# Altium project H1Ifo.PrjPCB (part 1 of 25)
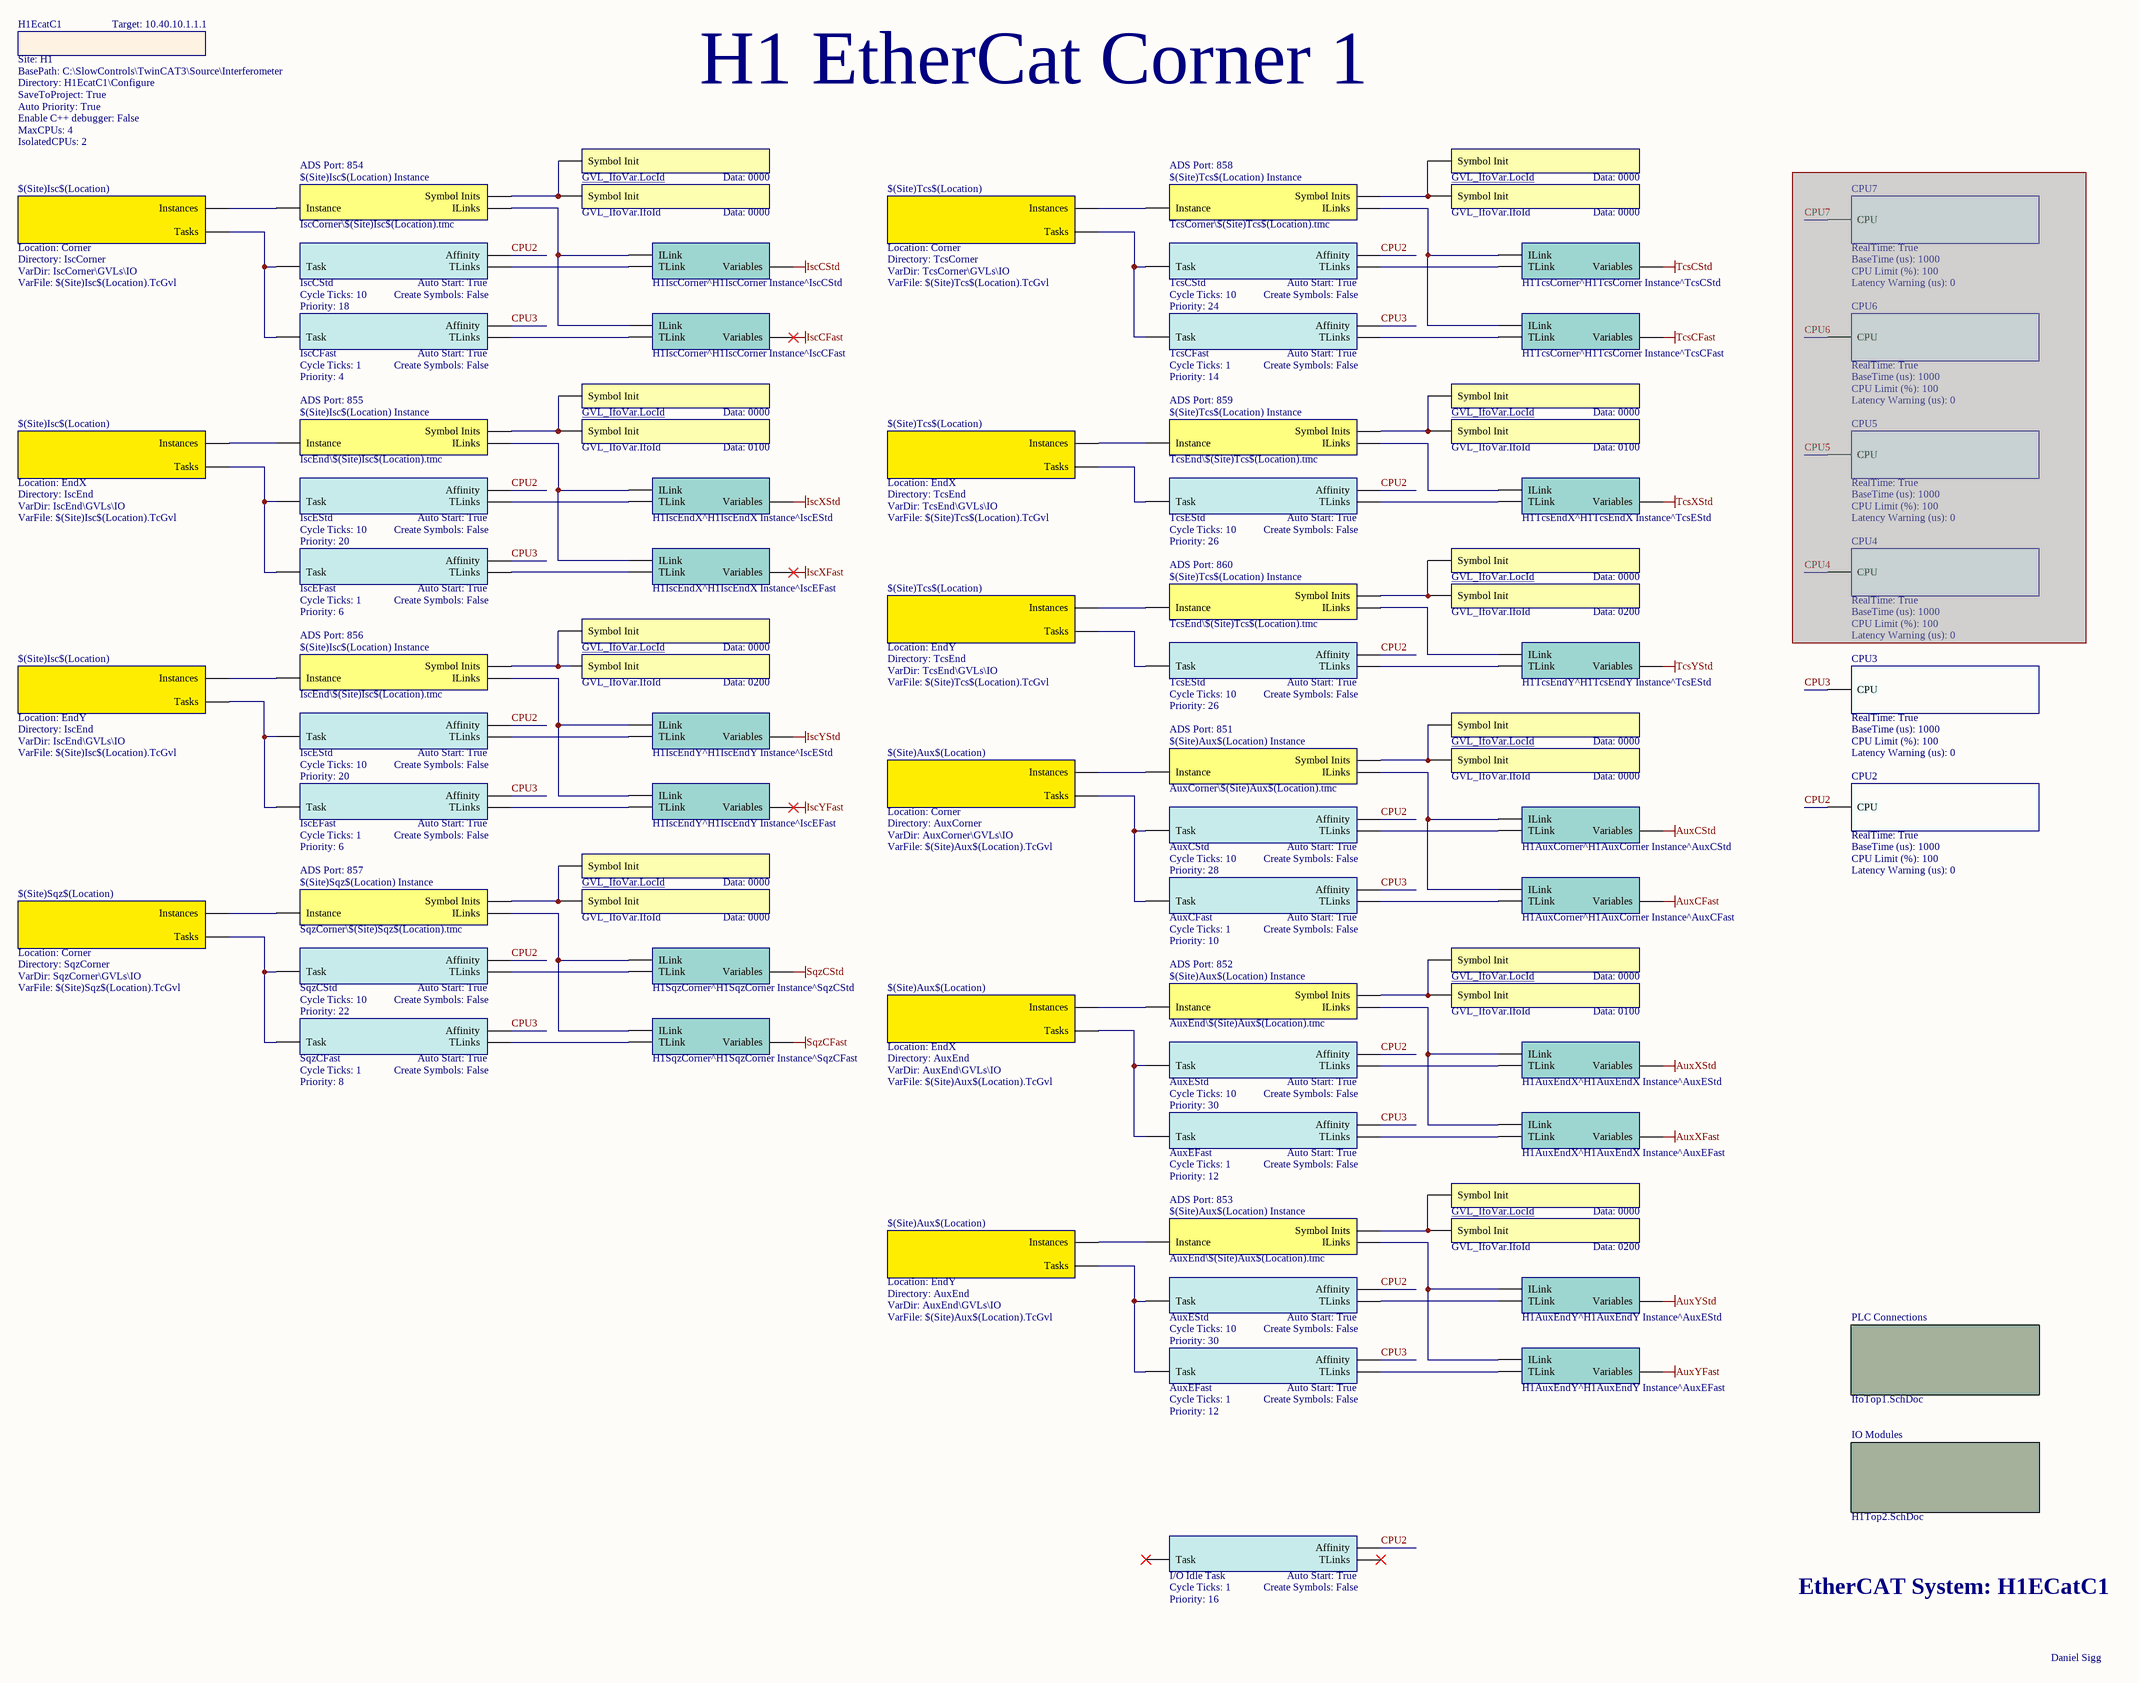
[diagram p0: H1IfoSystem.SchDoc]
Title: D1800185; Revision: 4
33 sheets, 2126 parts. Net scope: flat (ports and power ports of the same name join across sheets).
Sheets:
  H1IfoSystem.SchDoc
    IO Modules = H1Top2.SchDoc
      MSR Corner = IfoMsr1.SchDoc
      Aux Corner = IfoAux1.SchDoc
      PSL IO TCS Corner = IfoPsl.SchDoc
      TCS Corner = IfoTcs1.SchDoc
      ISC Common = IfoIsc1.SchDoc
      ISC Corner 2 = IfoIsc2A.SchDoc
      ISC Corner 2 = IfoIsc2B.SchDoc
      ISC Corner 3 = IfoIsc3.SchDoc
      ISC Corner 4 = IfoIsc4.SchDoc
      ISC Corner 5 = IfoIsc5A.SchDoc
      ISC Corner 5 = IfoIsc5B.SchDoc
      ISC Corner 6 = IfoIsc6.SchDoc
      SQZ Common = IfoSqz1.SchDoc
      SQZ 2 = IfoSqz2.SchDoc
      SQZ 3 = IfoSqz3A.SchDoc
      SQZ 3 = IfoSqz3B.SchDoc
      Remote EX = IfoEndX0.SchDoc
      EX Common = IfoEndX1.SchDoc
      EX 2 = IfoEndX2.SchDoc
      EX 3 = IfoEndX3.SchDoc
      Remote EY = IfoEndY0.SchDoc
      EY Common = IfoEndY1.SchDoc
      EY 2 = IfoEndY2.SchDoc
      EY 3 = IfoEndY3.SchDoc
      EX Aux = IfoEndXAux.SchDoc
      EY Aux = IfoEndYAux.SchDoc
      SQZ 4 = IfoSqz4A.SchDoc
      SQZ 4 = IfoSqz4B.SchDoc
      FC End = IfoFcEnd.SchDoc
      SQZ 5 = IfoSqz5.SchDoc
    PLC Connections = IfoTop1.SchDoc

## Sheet H1IfoSystem.SchDoc: D1800185
size C; Engineer: Daniel Sigg; DocumentNumber: 1; Revision: 4; SheetNumber: 1; SheetTotal: 31

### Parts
CPU2  RealTime: True  BaseTime (us): 1000  CPU Limit (%): 100  Latency Warning (us): 0  (hidden comment: CPU)  (mechanical)
CPU3  RealTime: True  BaseTime (us): 1000  CPU Limit (%): 100  Latency Warning (us): 0  (hidden comment: CPU)  (mechanical)
CPU4  RealTime: True  BaseTime (us): 1000  CPU Limit (%): 100  Latency Warning (us): 0  (hidden comment: CPU)  (mechanical)  (masked out: inside a compile mask, not in the netlist)
CPU5  RealTime: True  BaseTime (us): 1000  CPU Limit (%): 100  Latency Warning (us): 0  (hidden comment: CPU)  (mechanical)  (masked out: inside a compile mask, not in the netlist)
CPU6  RealTime: True  BaseTime (us): 1000  CPU Limit (%): 100  Latency Warning (us): 0  (hidden comment: CPU)  (mechanical)  (masked out: inside a compile mask, not in the netlist)
CPU7  RealTime: True  BaseTime (us): 1000  CPU Limit (%): 100  Latency Warning (us): 0  (hidden comment: CPU)  (mechanical)  (masked out: inside a compile mask, not in the netlist)
I1  $(Site)Isc$(Location) Instance  ADS Port: 854  Filename: IscCorner\$(Site)Isc$(Location).tmc  (mechanical)
I2  $(Site)Isc$(Location) Instance  ADS Port: 855  Filename: IscEnd\$(Site)Isc$(Location).tmc  (mechanical)
I3  $(Site)Isc$(Location) Instance  ADS Port: 856  Filename: IscEnd\$(Site)Isc$(Location).tmc  (mechanical)
I4  $(Site)Sqz$(Location) Instance  ADS Port: 857  Filename: SqzCorner\$(Site)Sqz$(Location).tmc  (mechanical)
I5  $(Site)Tcs$(Location) Instance  ADS Port: 858  Filename: TcsCorner\$(Site)Tcs$(Location).tmc  (mechanical)
I6  $(Site)Tcs$(Location) Instance  ADS Port: 859  Filename: TcsEnd\$(Site)Tcs$(Location).tmc  (mechanical)
I7  $(Site)Tcs$(Location) Instance  ADS Port: 860  Filename: TcsEnd\$(Site)Tcs$(Location).tmc  (mechanical)
I8  $(Site)Aux$(Location) Instance  ADS Port: 851  Filename: AuxCorner\$(Site)Aux$(Location).tmc  (mechanical)
I9  $(Site)Aux$(Location) Instance  ADS Port: 852  Filename: AuxEnd\$(Site)Aux$(Location).tmc  (mechanical)
I10  $(Site)Aux$(Location) Instance  ADS Port: 853  Filename: AuxEnd\$(Site)Aux$(Location).tmc  (mechanical)
PLC1  $(Site)Isc$(Location)  Directory: IscCorner  Location: Corner  VarFile: $(Site)Isc$(Location).TcGvl  VarDir: IscCorner\GVLs\IO  (mechanical)
PLC2  $(Site)Isc$(Location)  Directory: IscEnd  Location: EndX  VarFile: $(Site)Isc$(Location).TcGvl  VarDir: IscEnd\GVLs\IO  (mechanical)
PLC3  $(Site)Isc$(Location)  Directory: IscEnd  Location: EndY  VarFile: $(Site)Isc$(Location).TcGvl  VarDir: IscEnd\GVLs\IO  (mechanical)
PLC4  $(Site)Sqz$(Location)  Directory: SqzCorner  Location: Corner  VarFile: $(Site)Sqz$(Location).TcGvl  VarDir: SqzCorner\GVLs\IO  (mechanical)
PLC5  $(Site)Tcs$(Location)  Directory: TcsCorner  Location: Corner  VarFile: $(Site)Tcs$(Location).TcGvl  VarDir: TcsCorner\GVLs\IO  (mechanical)
PLC6  $(Site)Tcs$(Location)  Directory: TcsEnd  Location: EndX  VarFile: $(Site)Tcs$(Location).TcGvl  VarDir: TcsEnd\GVLs\IO  (mechanical)
PLC7  $(Site)Tcs$(Location)  Directory: TcsEnd  Location: EndY  VarFile: $(Site)Tcs$(Location).TcGvl  VarDir: TcsEnd\GVLs\IO  (mechanical)
PLC8  $(Site)Aux$(Location)  Directory: AuxCorner  Location: Corner  VarFile: $(Site)Aux$(Location).TcGvl  VarDir: AuxCorner\GVLs\IO  (mechanical)
PLC9  $(Site)Aux$(Location)  Directory: AuxEnd  Location: EndX  VarFile: $(Site)Aux$(Location).TcGvl  VarDir: AuxEnd\GVLs\IO  (mechanical)
PLC10  $(Site)Aux$(Location)  Directory: AuxEnd  Location: EndY  VarFile: $(Site)Aux$(Location).TcGvl  VarDir: AuxEnd\GVLs\IO  (mechanical)
S1  GVL_IfoVar.LocId  Data: 0000  (mechanical)
S2  GVL_IfoVar.IfoId  Data: 0000  (mechanical)
S3  GVL_IfoVar.LocId  Data: 0000  (mechanical)
S4  GVL_IfoVar.IfoId  Data: 0100  (mechanical)
S5  GVL_IfoVar.LocId  Data: 0000  (mechanical)
S6  GVL_IfoVar.IfoId  Data: 0200  (mechanical)
S7  GVL_IfoVar.LocId  Data: 0000  (mechanical)
S8  GVL_IfoVar.IfoId  Data: 0000  (mechanical)
S9  GVL_IfoVar.LocId  Data: 0000  (mechanical)
S10  GVL_IfoVar.IfoId  Data: 0000  (mechanical)
S11  GVL_IfoVar.LocId  Data: 0000  (mechanical)
S12  GVL_IfoVar.IfoId  Data: 0100  (mechanical)
S13  GVL_IfoVar.LocId  Data: 0000  (mechanical)
S14  GVL_IfoVar.IfoId  Data: 0200  (mechanical)
S15  GVL_IfoVar.LocId  Data: 0000  (mechanical)
S16  GVL_IfoVar.IfoId  Data: 0000  (mechanical)
S17  GVL_IfoVar.LocId  Data: 0000  (mechanical)
S18  GVL_IfoVar.IfoId  Data: 0100  (mechanical)
S19  GVL_IfoVar.LocId  Data: 0000  (mechanical)
S20  GVL_IfoVar.IfoId  Data: 0200  (mechanical)
System  H1EcatC1  Auto Priority: True  Enable C++ debugger: False  Directory: H1EcatC1\Configure  Target: 10.40.10.1.1.1  MaxCPUs: 4  IsolatedCPUs: 2  BasePath: C:\SlowControls\TwinCAT3\Source\Interferometer  Site: H1  (mechanical)
T1  IscCStd  Priority: 18  Cycle Ticks: 10  Auto Start: True  Create Symbols: False  (mechanical)
T2  IscCFast  Priority: 4  Cycle Ticks: 1  Auto Start: True  Create Symbols: False  (mechanical)
T3  IscEStd  Priority: 20  Cycle Ticks: 10  Auto Start: True  Create Symbols: False  (mechanical)
T4  IscEFast  Priority: 6  Cycle Ticks: 1  Auto Start: True  Create Symbols: False  (mechanical)
T5  IscEStd  Priority: 20  Cycle Ticks: 10  Auto Start: True  Create Symbols: False  (mechanical)
T6  IscEFast  Priority: 6  Cycle Ticks: 1  Auto Start: True  Create Symbols: False  (mechanical)
T7  SqzCStd  Priority: 22  Cycle Ticks: 10  Auto Start: True  Create Symbols: False  (mechanical)
T8  SqzCFast  Priority: 8  Cycle Ticks: 1  Auto Start: True  Create Symbols: False  (mechanical)
T9  H1IscCorner^H1IscCorner Instance^IscCStd  (mechanical)
T10  H1IscCorner^H1IscCorner Instance^IscCFast  (mechanical)
T11  H1IscEndX^H1IscEndX Instance^IscEStd  (mechanical)
T12  H1IscEndX^H1IscEndX Instance^IscEFast  (mechanical)
T13  H1IscEndY^H1IscEndY Instance^IscEStd  (mechanical)
T14  H1IscEndY^H1IscEndY Instance^IscEFast  (mechanical)
T15  H1SqzCorner^H1SqzCorner Instance^SqzCStd  (mechanical)
T16  H1SqzCorner^H1SqzCorner Instance^SqzCFast  (mechanical)
T17  TcsCStd  Priority: 24  Cycle Ticks: 10  Auto Start: True  Create Symbols: False  (mechanical)
T18  TcsEStd  Priority: 26  Cycle Ticks: 10  Auto Start: True  Create Symbols: False  (mechanical)
T19  TcsEStd  Priority: 26  Cycle Ticks: 10  Auto Start: True  Create Symbols: False  (mechanical)
T20  AuxCStd  Priority: 28  Cycle Ticks: 10  Auto Start: True  Create Symbols: False  (mechanical)
T21  AuxCFast  Priority: 10  Cycle Ticks: 1  Auto Start: True  Create Symbols: False  (mechanical)
T22  AuxEStd  Priority: 30  Cycle Ticks: 10  Auto Start: True  Create Symbols: False  (mechanical)
T23  AuxEFast  Priority: 12  Cycle Ticks: 1  Auto Start: True  Create Symbols: False  (mechanical)
T24  AuxEStd  Priority: 30  Cycle Ticks: 10  Auto Start: True  Create Symbols: False  (mechanical)
T25  AuxEFast  Priority: 12  Cycle Ticks: 1  Auto Start: True  Create Symbols: False  (mechanical)
T26  I/O Idle Task  Priority: 16  Cycle Ticks: 1  Auto Start: True  Create Symbols: False  (mechanical)
T27  H1TcsCorner^H1TcsCorner Instance^TcsCStd  (mechanical)
T28  H1TcsEndX^H1TcsEndX Instance^TcsEStd  (mechanical)
T29  H1TcsEndY^H1TcsEndY Instance^TcsEStd  (mechanical)
T30  H1AuxCorner^H1AuxCorner Instance^AuxCStd  (mechanical)
T31  H1AuxCorner^H1AuxCorner Instance^AuxCFast  (mechanical)
T32  H1AuxEndX^H1AuxEndX Instance^AuxEStd  (mechanical)
T33  H1AuxEndX^H1AuxEndX Instance^AuxEFast  (mechanical)
T34  H1AuxEndY^H1AuxEndY Instance^AuxEStd  (mechanical)
T35  H1AuxEndY^H1AuxEndY Instance^AuxEFast  (mechanical)
T36  TcsCFast  Priority: 14  Cycle Ticks: 1  Auto Start: True  Create Symbols: False  (mechanical)
T37  H1TcsCorner^H1TcsCorner Instance^TcsCFast  (mechanical)

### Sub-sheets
IO Modules = H1Top2.SchDoc: no entries
PLC Connections = IfoTop1.SchDoc: no entries

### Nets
AuxCFast: T31.0(Variables)
AuxCStd: T30.0(Variables)
AuxXFast: T33.0(Variables)
AuxXStd: T32.0(Variables)
AuxYFast: T35.0(Variables)
AuxYStd: T34.0(Variables)
IscCFast: T10.0(Variables)
IscCStd: T9.0(Variables)
IscXFast: T12.0(Variables)
IscXStd: T11.0(Variables)
IscYFast: T14.0(Variables)
IscYStd: T13.0(Variables)
SqzCFast: T16.0(Variables)
SqzCStd: T15.0(Variables)
TcsCFast: T37.0(Variables)
TcsCStd: T27.0(Variables)
TcsXStd: T28.0(Variables)
TcsYStd: T29.0(Variables)
CPU2: CPU2.0(CPU) T1.1(Affinity) T3.1(Affinity) T5.1(Affinity) T7.1(Affinity) T17.1(Affinity) T18.1(Affinity) T19.1(Affinity) T20.1(Affinity) T22.1(Affinity) T24.1(Affinity) T26.1(Affinity)
CPU3: CPU3.0(CPU) T2.1(Affinity) T4.1(Affinity) T6.1(Affinity) T8.1(Affinity) T21.1(Affinity) T23.1(Affinity) T25.1(Affinity) T36.1(Affinity)
NetI1_0: I1.0(Instance) PLC1.0(Instances)
NetI1_2: I1.2(ILinks) T9.1(ILink) T10.1(ILink)
NetI1_2: I1.2(Symbol_Inits) S1.99(Symbol_Init) S2.99(Symbol_Init)  [a separate net that carries the same name]
NetI2_0: I2.0(Instance) PLC2.0(Instances)
NetI2_2: I2.2(ILinks) T11.1(ILink) T12.1(ILink)
NetI2_2: I2.2(Symbol_Inits) S3.99(Symbol_Init) S4.99(Symbol_Init)  [a separate net that carries the same name]
NetI3_0: I3.0(Instance) PLC3.0(Instances)
NetI3_2: I3.2(ILinks) T13.1(ILink) T14.1(ILink)
NetI3_2: I3.2(Symbol_Inits) S5.99(Symbol_Init) S6.99(Symbol_Init)  [a separate net that carries the same name]
NetI4_0: I4.0(Instance) PLC4.0(Instances)
NetI4_2: I4.2(ILinks) T15.1(ILink) T16.1(ILink)
NetI4_2: I4.2(Symbol_Inits) S7.99(Symbol_Init) S8.99(Symbol_Init)  [a separate net that carries the same name]
NetI5_0: I5.0(Instance) PLC5.0(Instances)
NetI5_2: I5.2(Symbol_Inits) S9.99(Symbol_Init) S10.99(Symbol_Init)
NetI5_2: I5.2(ILinks) T27.1(ILink) T37.1(ILink)  [a separate net that carries the same name]
NetI6_0: I6.0(Instance) PLC6.0(Instances)
NetI6_2: I6.2(ILinks) T28.1(ILink)
NetI6_2: I6.2(Symbol_Inits) S11.99(Symbol_Init) S12.99(Symbol_Init)  [a separate net that carries the same name]
NetI7_0: I7.0(Instance) PLC7.0(Instances)
NetI7_2: I7.2(ILinks) T29.1(ILink)
NetI7_2: I7.2(Symbol_Inits) S13.99(Symbol_Init) S14.99(Symbol_Init)  [a separate net that carries the same name]
NetI8_0: I8.0(Instance) PLC8.0(Instances)
NetI8_2: I8.2(ILinks) T30.1(ILink) T31.1(ILink)
NetI8_2: I8.2(Symbol_Inits) S15.99(Symbol_Init) S16.99(Symbol_Init)  [a separate net that carries the same name]
NetI9_0: I9.0(Instance) PLC9.0(Instances)
NetI9_2: I9.2(ILinks) T32.1(ILink) T33.1(ILink)
NetI9_2: I9.2(Symbol_Inits) S17.99(Symbol_Init) S18.99(Symbol_Init)  [a separate net that carries the same name]
NetI10_0: I10.0(Instance) PLC10.0(Instances)
NetI10_2: I10.2(ILinks) T34.1(ILink) T35.1(ILink)
NetI10_2: I10.2(Symbol_Inits) S19.99(Symbol_Init) S20.99(Symbol_Init)  [a separate net that carries the same name]
NetPLC1_1: PLC1.1(Tasks) T1.0(Task) T2.0(Task)
NetPLC2_1: PLC2.1(Tasks) T3.0(Task) T4.0(Task)
NetPLC3_1: PLC3.1(Tasks) T5.0(Task) T6.0(Task)
NetPLC4_1: PLC4.1(Tasks) T7.0(Task) T8.0(Task)
NetPLC5_1: PLC5.1(Tasks) T17.0(Task) T36.0(Task)
NetPLC6_1: PLC6.1(Tasks) T18.0(Task)
NetPLC7_1: PLC7.1(Tasks) T19.0(Task)
NetPLC8_1: PLC8.1(Tasks) T20.0(Task) T21.0(Task)
NetPLC9_1: PLC9.1(Tasks) T22.0(Task) T23.0(Task)
NetPLC10_1: PLC10.1(Tasks) T24.0(Task) T25.0(Task)
NetT1_2: T1.2(TLinks) T9.2(TLink)
NetT2_2: T2.2(TLinks) T10.2(TLink)
NetT3_2: T3.2(TLinks) T11.2(TLink)
NetT4_2: T4.2(TLinks) T12.2(TLink)
NetT5_2: T5.2(TLinks) T13.2(TLink)
NetT6_2: T6.2(TLinks) T14.2(TLink)
NetT7_2: T7.2(TLinks) T15.2(TLink)
NetT8_2: T8.2(TLinks) T16.2(TLink)
NetT17_2: T17.2(TLinks) T27.2(TLink)
NetT18_2: T18.2(TLinks) T28.2(TLink)
NetT19_2: T19.2(TLinks) T29.2(TLink)
NetT20_2: T20.2(TLinks) T30.2(TLink)
NetT21_2: T21.2(TLinks) T31.2(TLink)
NetT22_2: T22.2(TLinks) T32.2(TLink)
NetT23_2: T23.2(TLinks) T33.2(TLink)
NetT24_2: T24.2(TLinks) T34.2(TLink)
NetT25_2: T25.2(TLinks) T35.2(TLink)
NetT36_2: T36.2(TLinks) T37.2(TLink)

Not connected (* = marked no-connect by the designer): T26 0(Task)* 2(TLinks)*

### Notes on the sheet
- H1 EtherCat Corner 1
- EtherCAT System: H1ECatC1
- Daniel Sigg

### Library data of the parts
CPU2-CPU7 = TwinCATCPU: TwinCAT CPU
I1 = TwinCATInstance: TwinCAT PLC Instance; Symbol Init: QOGVYBPF; PLC: H1IscCorner; Location: Corner
I2 = TwinCATInstance: TwinCAT PLC Instance; Symbol Init: ANWTYMNB; PLC: H1IscEndX; Location: EndX
I3 = TwinCATInstance: TwinCAT PLC Instance; Symbol Init: TKQDQPCD; PLC: H1IscEndY; Location: EndY
I4 = TwinCATInstance: TwinCAT PLC Instance; Symbol Init: JDCVMCFT; PLC: H1SqzCorner; Location: Corner
I5 = TwinCATInstance: TwinCAT PLC Instance; Symbol Init: PQEEGHBX; PLC: H1TcsCorner; Location: Corner
I6 = TwinCATInstance: TwinCAT PLC Instance; Symbol Init: PMAHGRIT; PLC: H1TcsEndX; Location: EndX
I7 = TwinCATInstance: TwinCAT PLC Instance; Symbol Init: QCDHSLLL; PLC: H1TcsEndY; Location: EndY
I8 = TwinCATInstance: TwinCAT PLC Instance; Symbol Init: FOFYGOIF; PLC: H1AuxCorner; Location: Corner
I9 = TwinCATInstance: TwinCAT PLC Instance; Symbol Init: VPBKJCNL; PLC: H1AuxEndX; Location: EndX
I10 = TwinCATInstance: TwinCAT PLC Instance; Symbol Init: HWRHWHNB; PLC: H1AuxEndY; Location: EndY
PLC1 = TwinCATPLC: TwinCAT PLC; Instance: GYFKFSOI
PLC2 = TwinCATPLC: TwinCAT PLC; Instance: EWVUFOBF
PLC3 = TwinCATPLC: TwinCAT PLC; Instance: NJXXMYFB
PLC4 = TwinCATPLC: TwinCAT PLC; Instance: GIVXPOYF
PLC5 = TwinCATPLC: TwinCAT PLC; Instance: MUFDHMNW
PLC6 = TwinCATPLC: TwinCAT PLC; Instance: TPTTRFUS
PLC7 = TwinCATPLC: TwinCAT PLC; Instance: BORUSAKV
PLC8 = TwinCATPLC: TwinCAT PLC; Instance: FFXNWLLD
PLC9 = TwinCATPLC: TwinCAT PLC; Instance: NTIEJDWE
PLC10 = TwinCATPLC: TwinCAT PLC; Instance: KMWKGJTW
S1 = TwinCATSymbol: TwinCAT Symbol Initialization; Next: KBGCXKHJ
S2 S4 S6 S8 S10 S12 S14 S16 S18 S20 = TwinCATSymbol: TwinCAT Symbol Initialization
S3 = TwinCATSymbol: TwinCAT Symbol Initialization; Next: RFHBSAYS
S5 = TwinCATSymbol: TwinCAT Symbol Initialization; Next: YLQCSWVN
S7 = TwinCATSymbol: TwinCAT Symbol Initialization; Next: LKBTSDNS
S9 = TwinCATSymbol: TwinCAT Symbol Initialization; Next: FADMXHAG
S11 = TwinCATSymbol: TwinCAT Symbol Initialization; Next: OKYYBMVQ
S13 = TwinCATSymbol: TwinCAT Symbol Initialization; Next: JGJNILQS
S15 = TwinCATSymbol: TwinCAT Symbol Initialization; Next: FCGACHJI
S17 = TwinCATSymbol: TwinCAT Symbol Initialization; Next: SEHPMEBM
S19 = TwinCATSymbol: TwinCAT Symbol Initialization; Next: LHVAWOAX
System = TwinCATSystem: TwinCAT System
T1 T3 T5 T7 T17-T20 T22 T24 T26 = TwinCATTask: TwinCAT Task; CPU: 2; BaseTime (100ns): 10000
T2 T4 T6 T8 T21 T23 T25 T36 = TwinCATTask: TwinCAT Task; CPU: 3; BaseTime (100ns): 10000
T9-T16 T27-T35 T37 = TwinCATLink: TwinCAT Variable Link

## Sheet H1Top2.SchDoc: D1800185
size C; DocumentNumber: 3; Revision: 4; SheetNumber: 3; SheetTotal: 31; pInstance: Corner
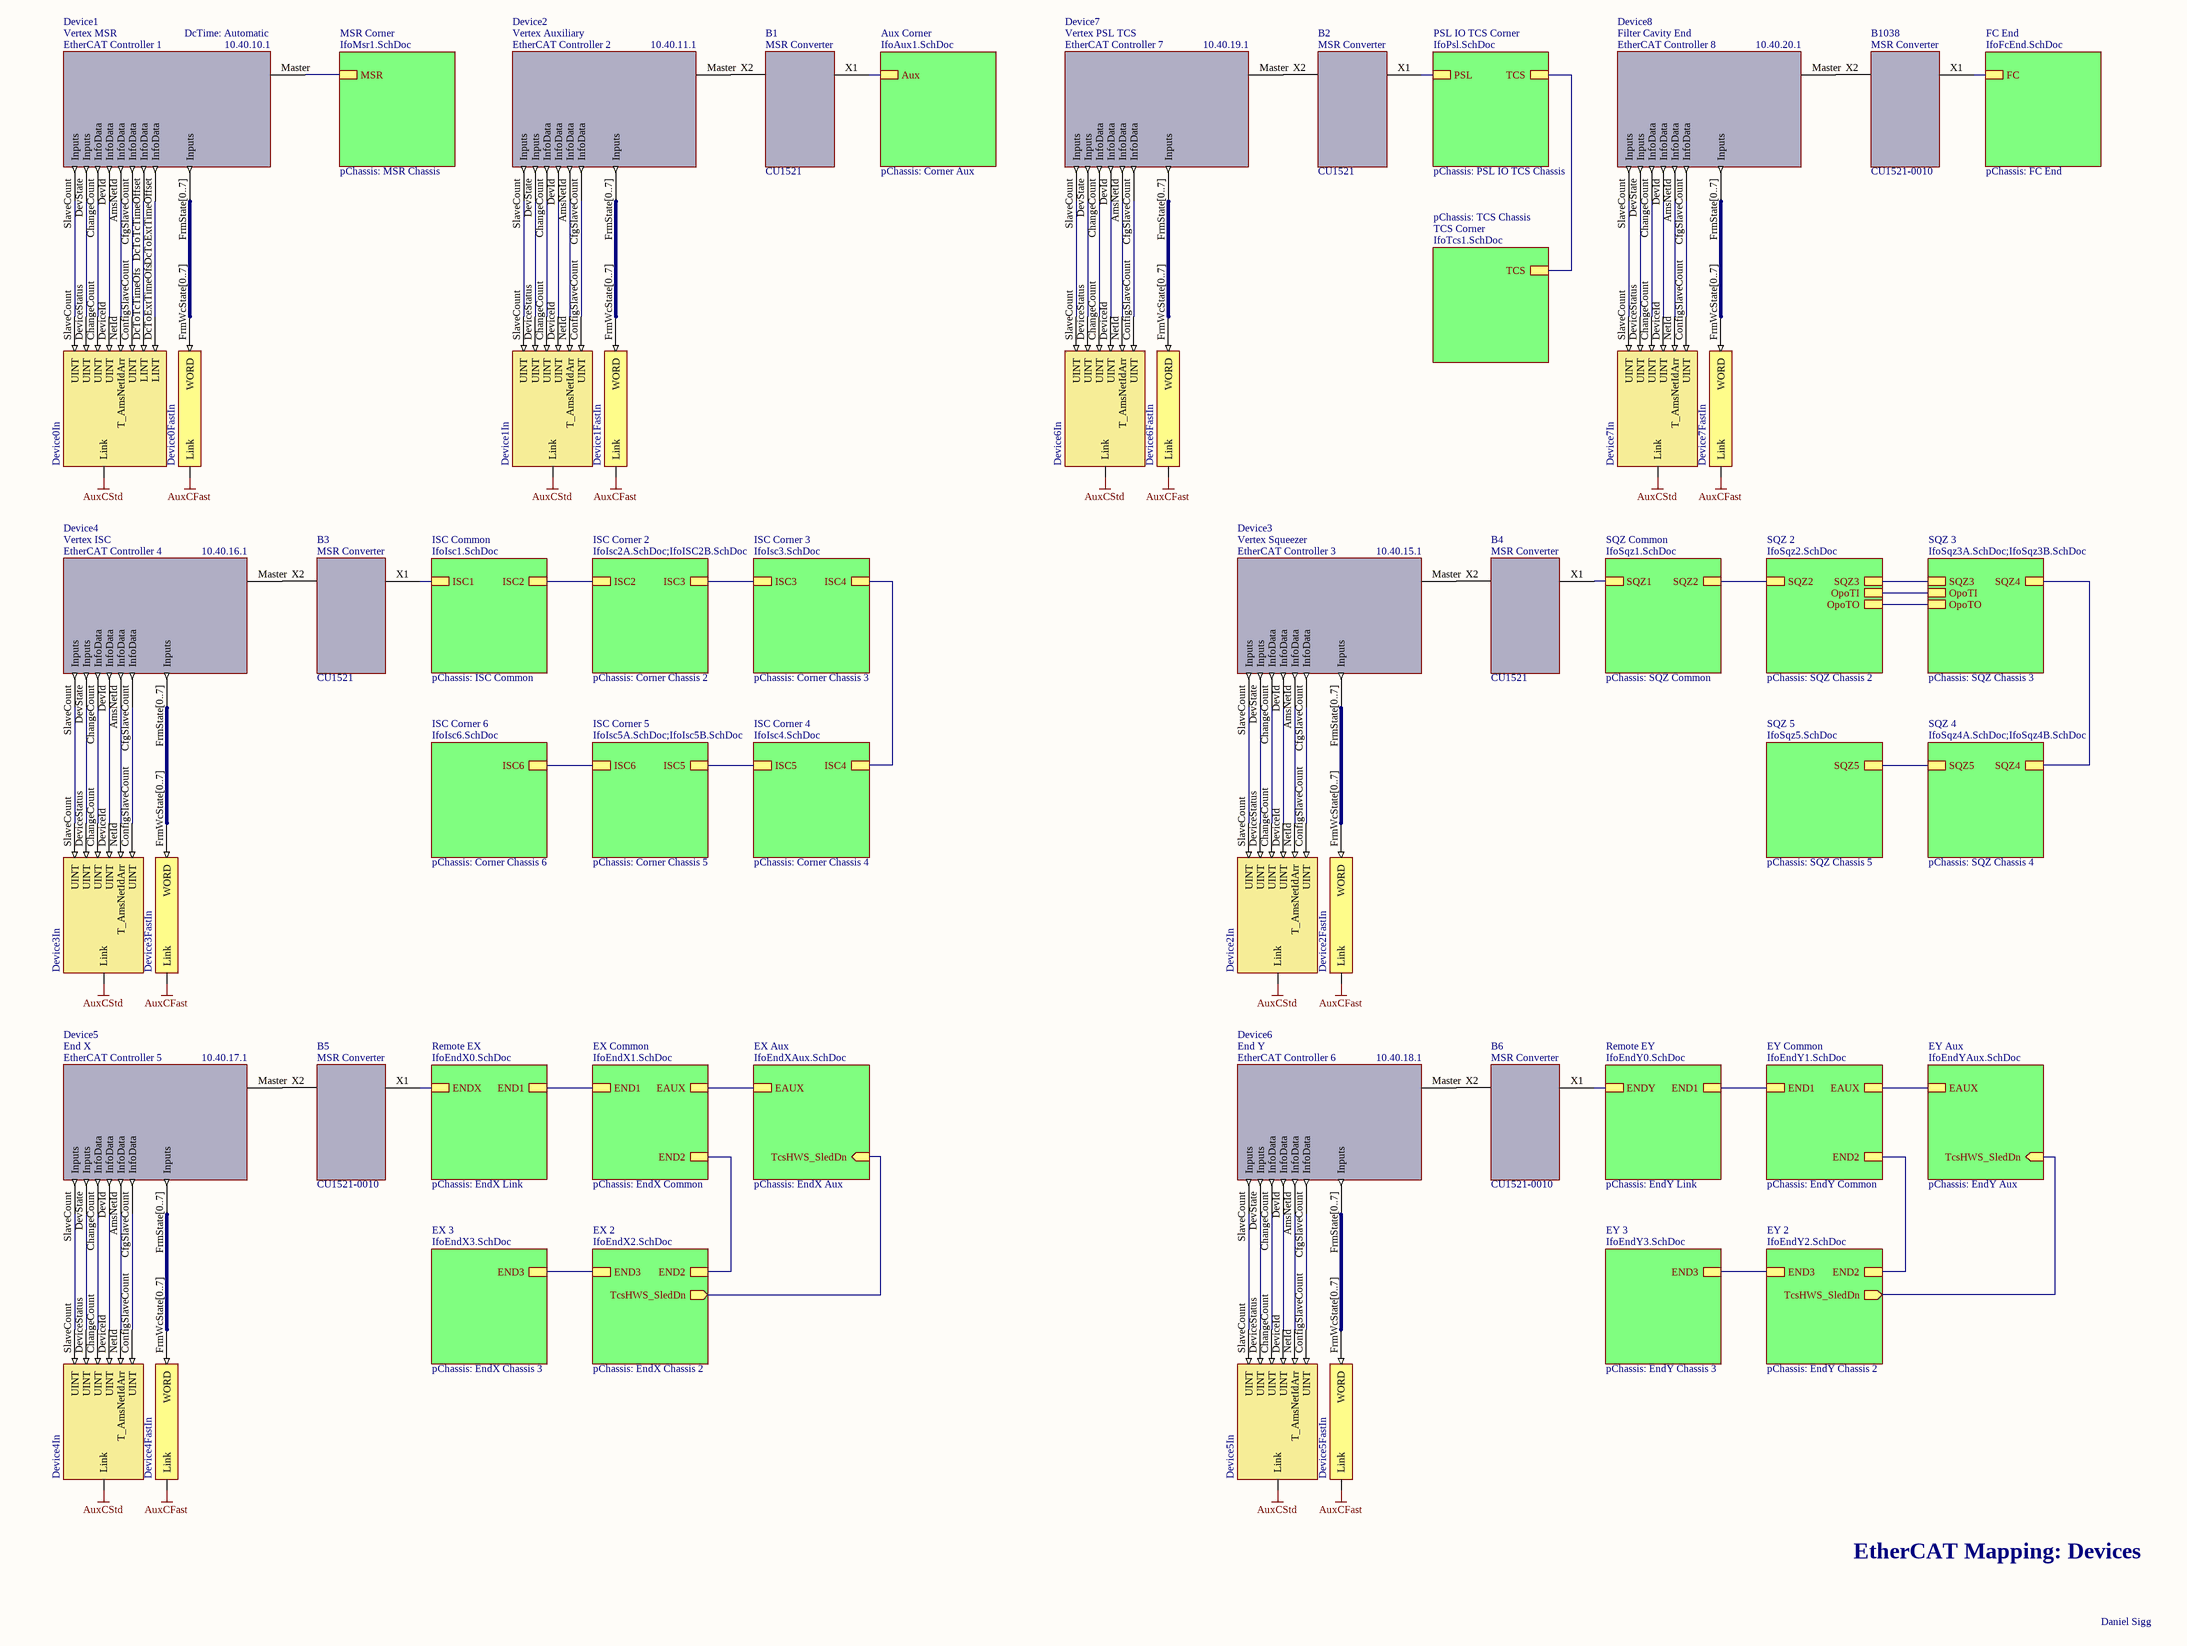
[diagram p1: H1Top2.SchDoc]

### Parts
B1  MSR Converter  Part Number: CU1521  (mechanical)
B2  MSR Converter  Part Number: CU1521  (mechanical)
B3  MSR Converter  Part Number: CU1521  (mechanical)
B4  MSR Converter  Part Number: CU1521  (mechanical)
B5  MSR Converter  Part Number: CU1521-0010  (mechanical)
B6  MSR Converter  Part Number: CU1521-0010  (mechanical)
B1038  MSR Converter  Part Number: CU1521-0010  (mechanical)
Device1  Vertex MSR  DcTime: Automatic  IPAddr: 10.40.10.1  DeviceDesc: EtherCAT Controller 1  (mechanical)
Device2  Vertex Auxiliary  IPAddr: 10.40.11.1  DeviceDesc: EtherCAT Controller 2  (mechanical)
Device3  Vertex Squeezer  IPAddr: 10.40.15.1  DeviceDesc: EtherCAT Controller 3  (mechanical)
Device4  Vertex ISC  IPAddr: 10.40.16.1  DeviceDesc: EtherCAT Controller 4  (mechanical)
Device5  End X  IPAddr: 10.40.17.1  DeviceDesc: EtherCAT Controller 5  (mechanical)
Device6  End Y  IPAddr: 10.40.18.1  DeviceDesc: EtherCAT Controller 6  (mechanical)
Device7  Vertex PSL TCS  IPAddr: 10.40.19.1  DeviceDesc: EtherCAT Controller 7  (mechanical)
Device8  Filter Cavity End  IPAddr: 10.40.20.1  DeviceDesc: EtherCAT Controller 8  (mechanical)
V81  Device0In  (no BOM)
V82  Device0FastIn  (no BOM)
V83  Device1In  (no BOM)
V84  Device1FastIn  (no BOM)
V85  Device6In  (no BOM)
V86  Device6FastIn  (no BOM)
V87  Device3In  (no BOM)
V88  Device3FastIn  (no BOM)
V89  Device2In  (no BOM)
V90  Device2FastIn  (no BOM)
V91  Device4In  (no BOM)
V92  Device4FastIn  (no BOM)
V93  Device5In  (no BOM)
V94  Device5FastIn  (no BOM)
V829  Device7In  (no BOM)
V830  Device7FastIn  (no BOM)

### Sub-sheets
Aux Corner = IfoAux1.SchDoc: Aux  | pChassis: Corner Aux
EX 2 = IfoEndX2.SchDoc: END2, END3, TcsHWS_SledDn (out)  | pChassis: EndX Chassis 2
EX 3 = IfoEndX3.SchDoc: END3  | pChassis: EndX Chassis 3
EX Aux = IfoEndXAux.SchDoc: EAUX, TcsHWS_SledDn (in)  | pChassis: EndX Aux
EX Common = IfoEndX1.SchDoc: END1, END2, EAUX  | pChassis: EndX Common
EY 2 = IfoEndY2.SchDoc: END2, END3, TcsHWS_SledDn (out)  | pChassis: EndY Chassis 2
EY 3 = IfoEndY3.SchDoc: END3  | pChassis: EndY Chassis 3
EY Aux = IfoEndYAux.SchDoc: EAUX, TcsHWS_SledDn (in)  | pChassis: EndY Aux
EY Common = IfoEndY1.SchDoc: END1, END2, EAUX  | pChassis: EndY Common
FC End = IfoFcEnd.SchDoc: FC  | pChassis: FC End
ISC Common = IfoIsc1.SchDoc: ISC1, ISC2  | pChassis: ISC Common
ISC Corner 2 = IfoIsc2A.SchDoc;IfoISC2B.SchDoc: ISC2, ISC3  | pChassis: Corner Chassis 2
ISC Corner 3 = IfoIsc3.SchDoc: ISC3, ISC4  | pChassis: Corner Chassis 3
ISC Corner 4 = IfoIsc4.SchDoc: ISC4, ISC5  | pChassis: Corner Chassis 4
ISC Corner 5 = IfoIsc5A.SchDoc;IfoIsc5B.SchDoc: ISC5, ISC6  | pChassis: Corner Chassis 5
ISC Corner 6 = IfoIsc6.SchDoc: ISC6  | pChassis: Corner Chassis 6
MSR Corner = IfoMsr1.SchDoc: MSR  | pChassis: MSR Chassis
PSL IO TCS Corner = IfoPsl.SchDoc: PSL, TCS  | pChassis: PSL IO TCS Chassis
Remote EX = IfoEndX0.SchDoc: ENDX, END1  | pChassis: EndX Link
Remote EY = IfoEndY0.SchDoc: ENDY, END1  | pChassis: EndY Link
SQZ 2 = IfoSqz2.SchDoc: SQZ2, SQZ3, OpoTI, OpoTO  | pChassis: SQZ Chassis 2
SQZ 3 = IfoSqz3A.SchDoc;IfoSqz3B.SchDoc: SQZ3, OpoTI, OpoTO, SQZ4  | pChassis: SQZ Chassis 3
SQZ 4 = IfoSqz4A.SchDoc;IfoSqz4B.SchDoc: SQZ4, SQZ5  | pChassis: SQZ Chassis 4
SQZ 5 = IfoSqz5.SchDoc: SQZ5  | pChassis: SQZ Chassis 5
SQZ Common = IfoSqz1.SchDoc: SQZ1, SQZ2  | pChassis: SQZ Common
TCS Corner = IfoTcs1.SchDoc: TCS  | pChassis: TCS Chassis

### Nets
AuxCFast: V82.?1(Link) V84.?1(Link) V86.?1(Link) V88.?1(Link) V90.?1(Link) V92.?1(Link) V94.?1(Link) V830.?1(Link)
AuxCStd: V81.?1(Link) V83.?1(Link) V85.?1(Link) V87.?1(Link) V89.?1(Link) V91.?1(Link) V93.?1(Link) V829.?1(Link)
NetB1_X1: B1.X1(B) ; sheet Aux Corner/Aux
NetB1_X2: B1.X2(A) Device2.Master(B)
NetB2_X1: B2.X1(B) ; sheet PSL IO TCS Corner/PSL
NetB2_X2: B2.X2(A) Device7.Master(B)
NetB3_X1: B3.X1(B) ; sheet ISC Common/ISC1
NetB3_X2: B3.X2(A) Device4.Master(B)
NetB4_X1: B4.X1(B) ; sheet SQZ Common/SQZ1
NetB4_X2: B4.X2(A) Device3.Master(B)
NetB5_X1: B5.X1(B) ; sheet Remote EX/ENDX
NetB5_X2: B5.X2(A) Device5.Master(B)
NetB6_X1: B6.X1(B) ; sheet Remote EY/ENDY
NetB6_X2: B6.X2(A) Device6.Master(B)
NetB1038_X1: B1038.X1(B) ; sheet FC End/FC
NetB1038_X2: B1038.X2(A) Device8.Master(B)
NetDevice1_AmsNetId: Device1.AmsNetId(InfoData) V81.NetId(T_AmsNetIdArr)
NetDevice1_CfgSlaveCount: Device1.CfgSlaveCount(InfoData) V81.ConfigSlaveCount(UINT)
NetDevice1_ChangeCount: Device1.ChangeCount(InfoData) V81.ChangeCount(UINT)
NetDevice1_DcToExtTimeOffset: Device1.DcToExtTimeOffset(InfoData) V81.DcToExtTimeOfs(LINT)
NetDevice1_DcToTcTimeOffset: Device1.DcToTcTimeOffset(InfoData) V81.DcToTcTimeOfs(LINT)
NetDevice1_DevId: Device1.DevId(InfoData) V81.DeviceId(UINT)
NetDevice1_DevState: Device1.DevState(Inputs) V81.DeviceStatus(UINT)
NetDevice1_FrmState[0..7]: Device1.FrmState[0..7](Inputs) V82.FrmWcState[0..7](WORD)
NetDevice1_Master: Device1.Master(B) ; sheet MSR Corner/MSR
NetDevice1_SlaveCount: Device1.SlaveCount(Inputs) V81.SlaveCount(UINT)
NetDevice2_AmsNetId: Device2.AmsNetId(InfoData) V83.NetId(T_AmsNetIdArr)
NetDevice2_CfgSlaveCount: Device2.CfgSlaveCount(InfoData) V83.ConfigSlaveCount(UINT)
NetDevice2_ChangeCount: Device2.ChangeCount(InfoData) V83.ChangeCount(UINT)
NetDevice2_DevId: Device2.DevId(InfoData) V83.DeviceId(UINT)
NetDevice2_DevState: Device2.DevState(Inputs) V83.DeviceStatus(UINT)
NetDevice2_FrmState[0..7]: Device2.FrmState[0..7](Inputs) V84.FrmWcState[0..7](WORD)
NetDevice2_SlaveCount: Device2.SlaveCount(Inputs) V83.SlaveCount(UINT)
NetDevice3_AmsNetId: Device3.AmsNetId(InfoData) V89.NetId(T_AmsNetIdArr)
NetDevice3_CfgSlaveCount: Device3.CfgSlaveCount(InfoData) V89.ConfigSlaveCount(UINT)
NetDevice3_ChangeCount: Device3.ChangeCount(InfoData) V89.ChangeCount(UINT)
NetDevice3_DevId: Device3.DevId(InfoData) V89.DeviceId(UINT)
NetDevice3_DevState: Device3.DevState(Inputs) V89.DeviceStatus(UINT)
NetDevice3_FrmState[0..7]: Device3.FrmState[0..7](Inputs) V90.FrmWcState[0..7](WORD)
NetDevice3_SlaveCount: Device3.SlaveCount(Inputs) V89.SlaveCount(UINT)
NetDevice4_AmsNetId: Device4.AmsNetId(InfoData) V87.NetId(T_AmsNetIdArr)
NetDevice4_CfgSlaveCount: Device4.CfgSlaveCount(InfoData) V87.ConfigSlaveCount(UINT)
NetDevice4_ChangeCount: Device4.ChangeCount(InfoData) V87.ChangeCount(UINT)
NetDevice4_DevId: Device4.DevId(InfoData) V87.DeviceId(UINT)
NetDevice4_DevState: Device4.DevState(Inputs) V87.DeviceStatus(UINT)
NetDevice4_FrmState[0..7]: Device4.FrmState[0..7](Inputs) V88.FrmWcState[0..7](WORD)
NetDevice4_SlaveCount: Device4.SlaveCount(Inputs) V87.SlaveCount(UINT)
NetDevice5_AmsNetId: Device5.AmsNetId(InfoData) V91.NetId(T_AmsNetIdArr)
NetDevice5_CfgSlaveCount: Device5.CfgSlaveCount(InfoData) V91.ConfigSlaveCount(UINT)
NetDevice5_ChangeCount: Device5.ChangeCount(InfoData) V91.ChangeCount(UINT)
NetDevice5_DevId: Device5.DevId(InfoData) V91.DeviceId(UINT)
NetDevice5_DevState: Device5.DevState(Inputs) V91.DeviceStatus(UINT)
NetDevice5_FrmState[0..7]: Device5.FrmState[0..7](Inputs) V92.FrmWcState[0..7](WORD)
NetDevice5_SlaveCount: Device5.SlaveCount(Inputs) V91.SlaveCount(UINT)
NetDevice6_AmsNetId: Device6.AmsNetId(InfoData) V93.NetId(T_AmsNetIdArr)
NetDevice6_CfgSlaveCount: Device6.CfgSlaveCount(InfoData) V93.ConfigSlaveCount(UINT)
NetDevice6_ChangeCount: Device6.ChangeCount(InfoData) V93.ChangeCount(UINT)
NetDevice6_DevId: Device6.DevId(InfoData) V93.DeviceId(UINT)
NetDevice6_DevState: Device6.DevState(Inputs) V93.DeviceStatus(UINT)
NetDevice6_FrmState[0..7]: Device6.FrmState[0..7](Inputs) V94.FrmWcState[0..7](WORD)
NetDevice6_SlaveCount: Device6.SlaveCount(Inputs) V93.SlaveCount(UINT)
NetDevice7_AmsNetId: Device7.AmsNetId(InfoData) V85.NetId(T_AmsNetIdArr)
NetDevice7_CfgSlaveCount: Device7.CfgSlaveCount(InfoData) V85.ConfigSlaveCount(UINT)
NetDevice7_ChangeCount: Device7.ChangeCount(InfoData) V85.ChangeCount(UINT)
NetDevice7_DevId: Device7.DevId(InfoData) V85.DeviceId(UINT)
NetDevice7_DevState: Device7.DevState(Inputs) V85.DeviceStatus(UINT)
NetDevice7_FrmState[0..7]: Device7.FrmState[0..7](Inputs) V86.FrmWcState[0..7](WORD)
NetDevice7_SlaveCount: Device7.SlaveCount(Inputs) V85.SlaveCount(UINT)
NetDevice8_AmsNetId: Device8.AmsNetId(InfoData) V829.NetId(T_AmsNetIdArr)
NetDevice8_CfgSlaveCount: Device8.CfgSlaveCount(InfoData) V829.ConfigSlaveCount(UINT)
NetDevice8_ChangeCount: Device8.ChangeCount(InfoData) V829.ChangeCount(UINT)
NetDevice8_DevId: Device8.DevId(InfoData) V829.DeviceId(UINT)
NetDevice8_DevState: Device8.DevState(Inputs) V829.DeviceStatus(UINT)
NetDevice8_FrmState[0..7]: Device8.FrmState[0..7](Inputs) V830.FrmWcState[0..7](WORD)
NetDevice8_SlaveCount: Device8.SlaveCount(Inputs) V829.SlaveCount(UINT)
(unnamed): sheet PSL IO TCS Corner/TCS, sheet TCS Corner/TCS
(unnamed): sheet ISC Common/ISC2, sheet ISC Corner 2/ISC2  [a separate net that carries the same name]
(unnamed): sheet ISC Corner 2/ISC3, sheet ISC Corner 3/ISC3  [a separate net that carries the same name]
(unnamed): sheet ISC Corner 3/ISC4, sheet ISC Corner 4/ISC4  [a separate net that carries the same name]
(unnamed): sheet ISC Corner 4/ISC5, sheet ISC Corner 5/ISC5  [a separate net that carries the same name]
(unnamed): sheet ISC Corner 5/ISC6, sheet ISC Corner 6/ISC6  [a separate net that carries the same name]
(unnamed): sheet SQZ Common/SQZ2, sheet SQZ 2/SQZ2  [a separate net that carries the same name]
(unnamed): sheet SQZ 2/SQZ3, sheet SQZ 3/SQZ3  [a separate net that carries the same name]
(unnamed): sheet SQZ 2/OpoTI, sheet SQZ 3/OpoTI  [a separate net that carries the same name]
(unnamed): sheet SQZ 2/OpoTO, sheet SQZ 3/OpoTO  [a separate net that carries the same name]
(unnamed): sheet SQZ 3/SQZ4, sheet SQZ 4/SQZ4  [a separate net that carries the same name]
(unnamed): sheet Remote EX/END1, sheet EX Common/END1  [a separate net that carries the same name]
(unnamed): sheet EX Common/END2, sheet EX 2/END2  [a separate net that carries the same name]
(unnamed): sheet EX Common/EAUX, sheet EX Aux/EAUX  [a separate net that carries the same name]
(unnamed): sheet EX 2/END3, sheet EX 3/END3  [a separate net that carries the same name]
(unnamed): sheet EX 2/TcsHWS_SledDn, sheet EX Aux/TcsHWS_SledDn  [a separate net that carries the same name]
(unnamed): sheet Remote EY/END1, sheet EY Common/END1  [a separate net that carries the same name]
(unnamed): sheet EY Common/END2, sheet EY 2/END2  [a separate net that carries the same name]
(unnamed): sheet EY Common/EAUX, sheet EY Aux/EAUX  [a separate net that carries the same name]
(unnamed): sheet EY 2/END3, sheet EY 3/END3  [a separate net that carries the same name]
(unnamed): sheet EY 2/TcsHWS_SledDn, sheet EY Aux/TcsHWS_SledDn  [a separate net that carries the same name]
(unnamed): sheet SQZ 4/SQZ5, sheet SQZ 5/SQZ5  [a separate net that carries the same name]

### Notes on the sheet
- EtherCAT Mapping: Devices
- Daniel Sigg

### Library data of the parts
B1 = MediaConverterCAT5toFiber: EtherCAT Media Converter; BoxType: Box; BoxNextB: RINAXMQE; BoxPrev: QDRPAMHP; PortPrevFull: 1000/; Fullname: TIID^Vertex Auxiliary (EtherCAT)^MSR Converter (CU1521); BoxAddr: 1001; Disabled: False
B2 = MediaConverterCAT5toFiber: EtherCAT Media Converter; BoxType: Box; BoxNextB: MGVQPUOL; BoxPrev: FVUSGNMR; PortPrevFull: 1000/; Fullname: TIID^Vertex PSL TCS (EtherCAT)^MSR Converter (CU1521); BoxAddr: 1001; Disabled: False
B3 = MediaConverterCAT5toFiber: EtherCAT Media Converter; BoxType: Box; BoxNextB: SGTCQRGF; BoxPrev: QYLLYTFA; PortPrevFull: 1000/; Fullname: TIID^Vertex ISC (EtherCAT)^MSR Converter (CU1521); BoxAddr: 1001; Disabled: False
B4 = MediaConverterCAT5toFiber: EtherCAT Media Converter; BoxType: Box; BoxNextB: STIDPCUW; BoxPrev: DGEHNNHI; PortPrevFull: 1000/; Fullname: TIID^Vertex Squeezer (EtherCAT)^MSR Converter (CU1521); BoxAddr: 1001; Disabled: False
B5 = MediaConverterCAT5toFiber: EtherCAT Media Converter; BoxType: Box; BoxNextB: PMEMEWCT; BoxPrev: QHBFWHLA; PortPrevFull: 1000/; Fullname: TIID^End X (EtherCAT)^MSR Converter (CU1521-0010); BoxAddr: 1001; Disabled: False
B6 = MediaConverterCAT5toFiber: EtherCAT Media Converter; BoxType: Box; BoxNextB: JHYOYQCQ; BoxPrev: MPRKTEYT; PortPrevFull: 1000/; Fullname: TIID^End Y (EtherCAT)^MSR Converter (CU1521-0010); BoxAddr: 1001; Disabled: False
B1038 = MediaConverterCAT5toFiber: EtherCAT Media Converter; BoxType: Box; BoxNextB: PXLUFAHI; BoxPrev: RIFLPVHI; PortPrevFull: 1000/; Fullname: TIID^Filter Cavity End (EtherCAT)^MSR Converter (CU1521-0010); BoxAddr: 1001; Disabled: False
Device1 = EtherCATMasterTimingB: EtherCAT Master; Part Number: FC9022; DeviceData: 0001053F992A; BoxNextB: DRMHDDTT; Fullname: TIID^Vertex MSR (EtherCAT); BoxSubType: 111; Disabled: False
Device2 = EtherCATMaster: EtherCAT Master; Part Number: FC9022; DeviceData: 0001053F992B; BoxNextB: XNQPCNPO; Fullname: TIID^Vertex Auxiliary (EtherCAT); BoxSubType: 111; Disabled: False
Device3 = EtherCATMaster: EtherCAT Master; Part Number: FC9022; DeviceData: 0001053F990B; BoxNextB: AUFRGGIT; Fullname: TIID^Vertex Squeezer (EtherCAT); BoxSubType: 111; Disabled: False
Device4 = EtherCATMaster: EtherCAT Master; Part Number: FC9022; DeviceData: 0001053F990A; BoxNextB: LUHLLVRJ; Fullname: TIID^Vertex ISC (EtherCAT); BoxSubType: 111; Disabled: False
Device5 = EtherCATMaster: EtherCAT Master; Part Number: FC9022; DeviceData: 0001053F9908; BoxNextB: JGFIEUEO; Fullname: TIID^End X (EtherCAT); BoxSubType: 111; Disabled: False
Device6 = EtherCATMaster: EtherCAT Master; Part Number: FC9022; DeviceData: 0001053F9909; BoxNextB: MULTFLPP; Fullname: TIID^End Y (EtherCAT); BoxSubType: 111; Disabled: False
Device7 = EtherCATMaster: EtherCAT Master; Part Number: FC9022; DeviceData: 0001053F9929; BoxNextB: KEYKBHHX; Fullname: TIID^Vertex PSL TCS (EtherCAT); BoxSubType: 111; Disabled: False
Device8 = EtherCATMaster: EtherCAT Master; Part Number: FC9022; DeviceData: 0001053F9928; BoxNextB: KMRKRJWW; Fullname: TIID^Filter Cavity End (EtherCAT); BoxSubType: 111; Disabled: False
V81 = PLCInfo_MasterInfoInStructB: MasterInfoInStruct; BoxType: Variable; Instance: H1AuxCorner Instance; PLC: H1AuxCorner; Task: AuxCStd
V82 = PLCInfo_MasterInfoFastInStruct: MasterInfoFastInStruct; BoxType: Variable; Instance: H1AuxCorner Instance; PLC: H1AuxCorner; Task: AuxCFast
V83 V85 V87 V89 V91 V93 V829 = PLCInfo_MasterInfoInStruct: MasterInfoInStruct; PLC: H1AuxCorner; Task: AuxCStd; BoxType: Variable; Instance: H1AuxCorner Instance
V84 V86 V88 V90 V92 V94 V830 = PLCInfo_MasterInfoFastInStruct: MasterInfoFastInStruct; PLC: H1AuxCorner; Task: AuxCFast; BoxType: Variable; Instance: H1AuxCorner Instance

## Sheet IfoMsr1.SchDoc: D1800185
size C; Engineer: Daniel Sigg; DocumentNumber: 4; Revision: 4; SheetNumber: 4; SheetTotal: 8
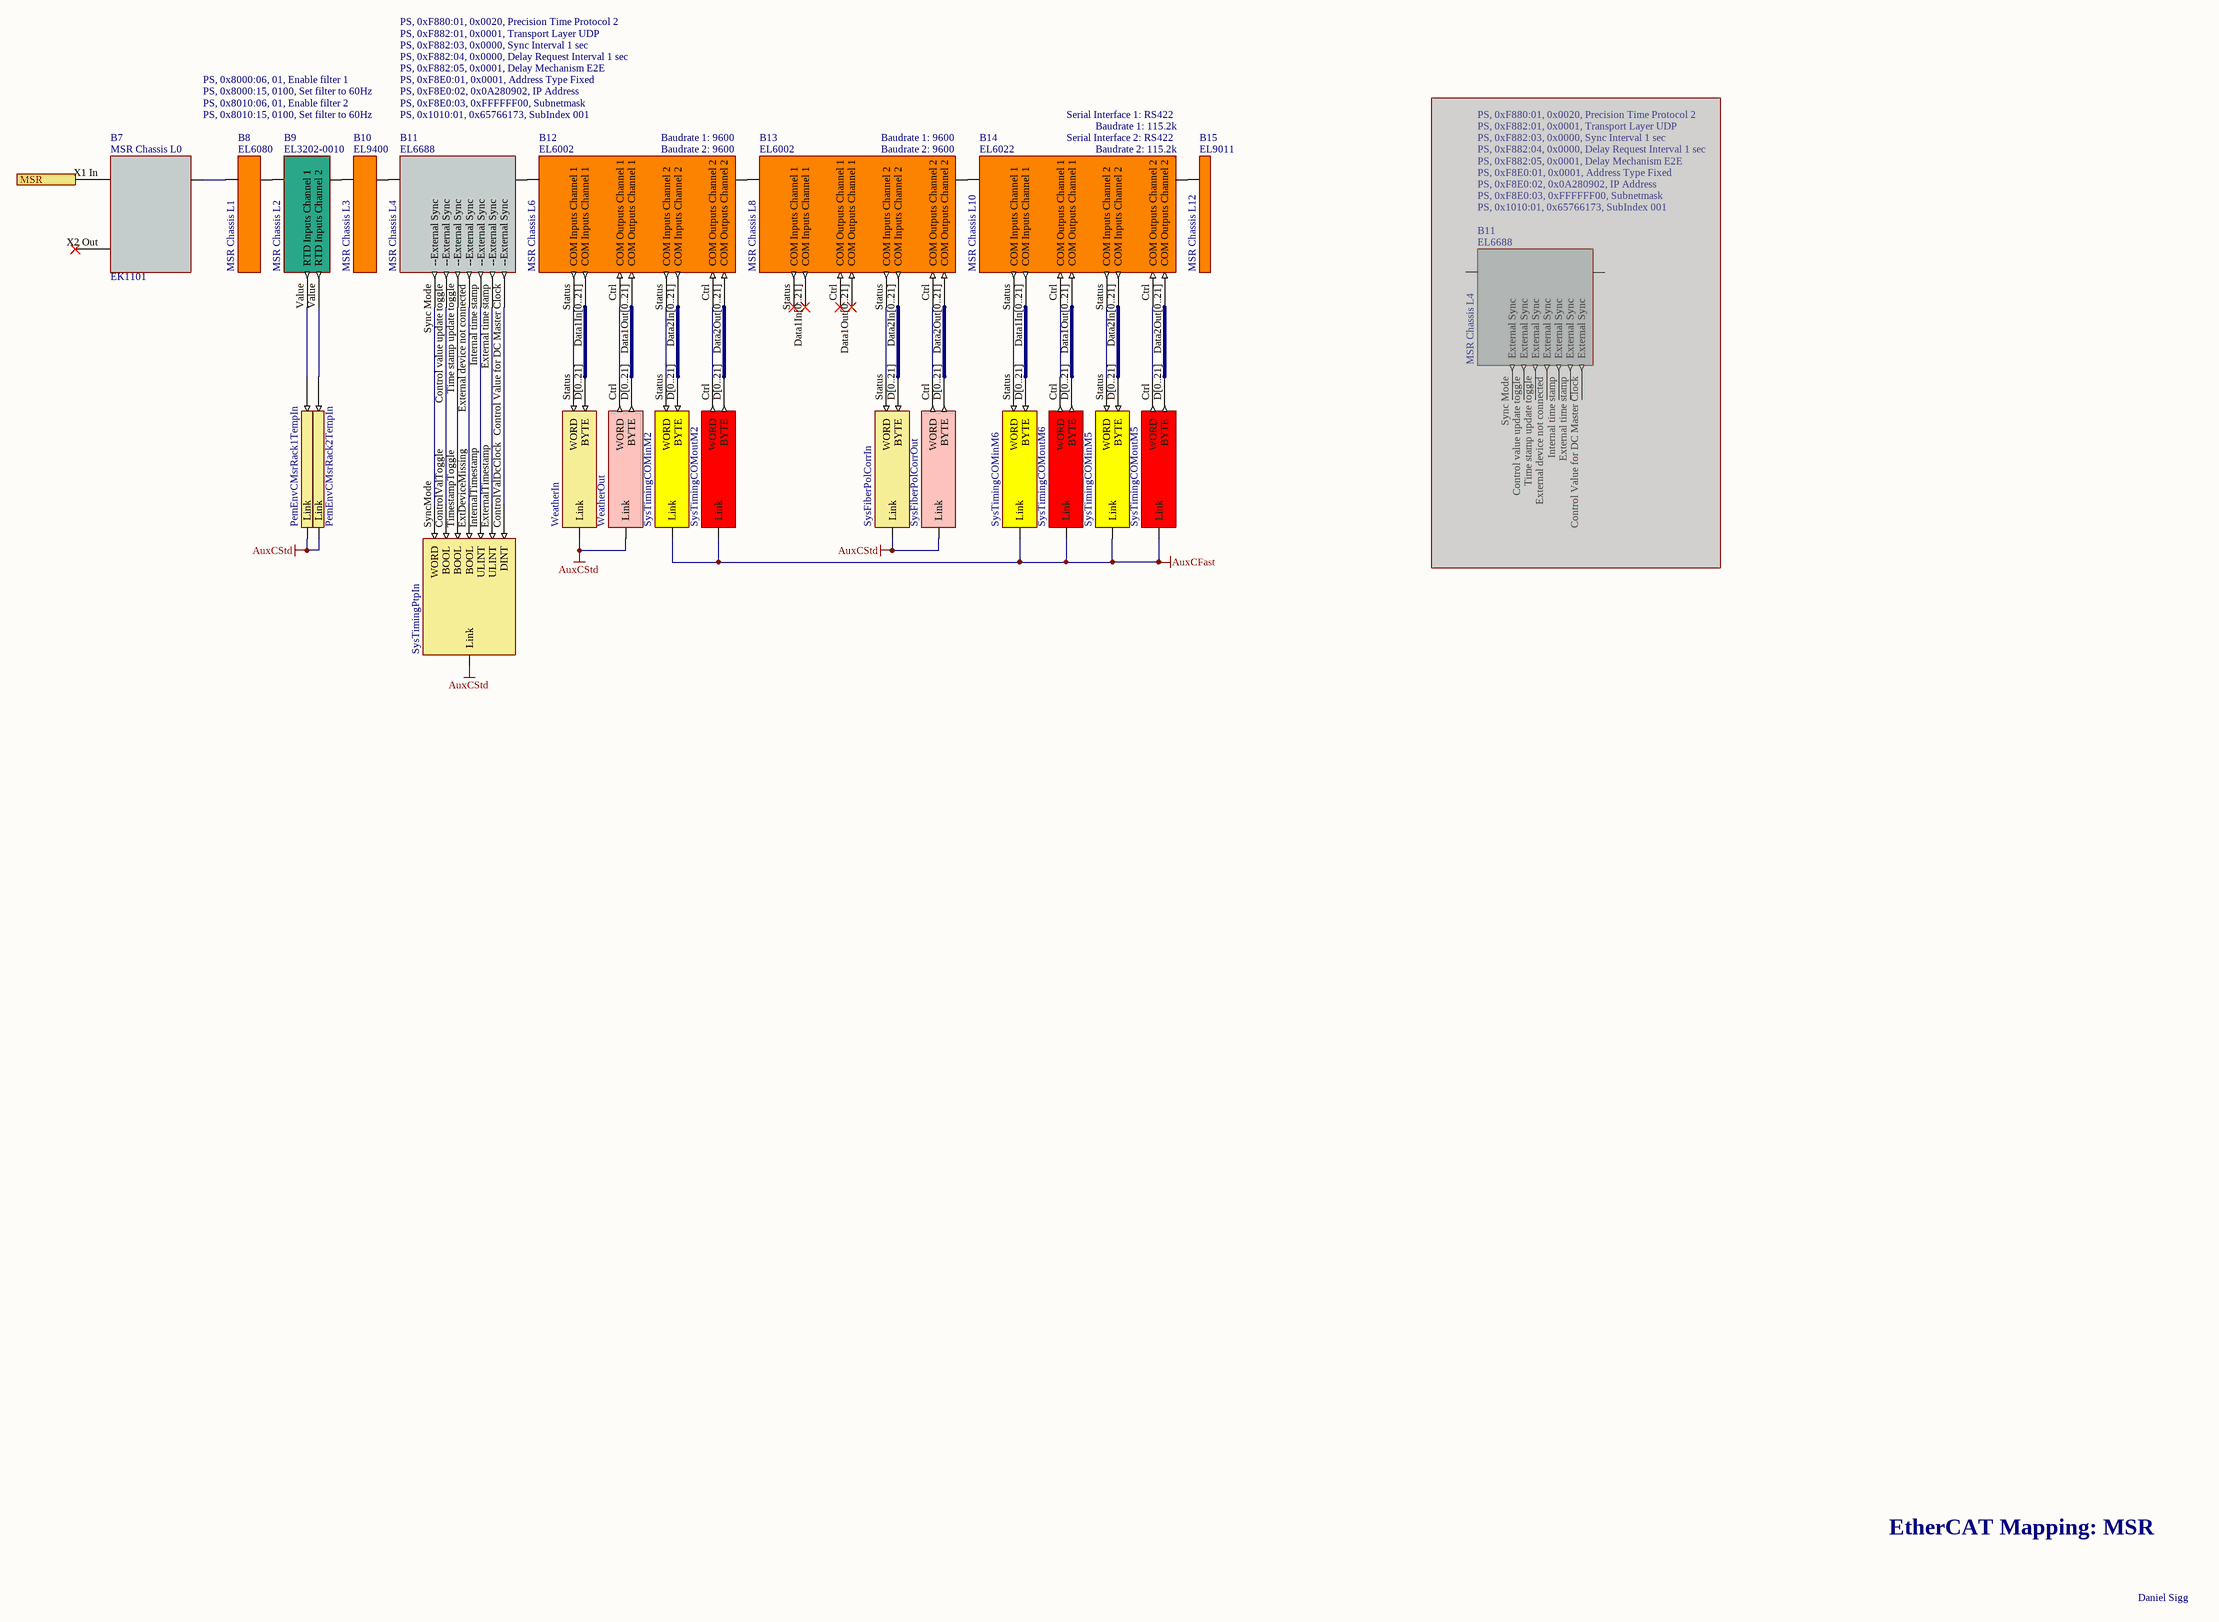
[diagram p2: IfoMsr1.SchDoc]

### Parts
(Parts that share a designator on the sheet are numbered #1, #2 ... from top to bottom, then left to right.)
B7  MSR Chassis L0  Part Number: EK1101  (mechanical)
B8  MSR Chassis L1  Part Number: EL6080  (mechanical)
B9  MSR Chassis L2  Part Number: EL3202-0010  Init0Cmd: PS, 0x8000:06, 01, Enable filter 1  Init1Cmd: PS, 0x8000:15, 0100, Set filter to 60Hz  Init2Cmd: PS, 0x8010:06, 01, Enable filter 2  Init3Cmd: PS, 0x8010:15, 0100, Set filter to 60Hz  (mechanical)
B10  MSR Chassis L3  Part Number: EL9400  (mechanical)
B11#1  MSR Chassis L4  Init3Cmd: PS, 0xF882:04, 0x0000, Delay Request Interval 1 sec  Init4Cmd: PS, 0xF882:05, 0x0001, Delay Mechanism E2E  Init5Cmd: PS, 0xF8E0:01, 0x0001, Address Type Fixed  Init6Cmd: PS, 0xF8E0:02, 0x0A280902, IP Address  Init7Cmd: PS, 0xF8E0:03, 0xFFFFFF00, Subnetmask  Init8Cmd: PS, 0x1010:01, 0x65766173, SubIndex 001  Init2Cmd: PS, 0xF882:03, 0x0000, Sync Interval 1 sec  Init1Cmd: PS, 0xF882:01, 0x0001, Transport Layer UDP  Init0Cmd: PS, 0xF880:01, 0x0020, Precision Time Protocol 2  Part Number: EL6688  (mechanical)
B11#2  MSR Chassis L4  Init3Cmd: PS, 0xF882:04, 0x0000, Delay Request Interval 1 sec  Init4Cmd: PS, 0xF882:05, 0x0001, Delay Mechanism E2E  Init5Cmd: PS, 0xF8E0:01, 0x0001, Address Type Fixed  Init6Cmd: PS, 0xF8E0:02, 0x0A280902, IP Address  Init7Cmd: PS, 0xF8E0:03, 0xFFFFFF00, Subnetmask  Init8Cmd: PS, 0x1010:01, 0x65766173, SubIndex 001  Init2Cmd: PS, 0xF882:03, 0x0000, Sync Interval 1 sec  Init1Cmd: PS, 0xF882:01, 0x0001, Transport Layer UDP  Init0Cmd: PS, 0xF880:01, 0x0020, Precision Time Protocol 2  Part Number: EL6688  (mechanical)  (masked out: inside a compile mask, not in the netlist)
B12  MSR Chassis L6  Part Number: EL6002  Baudrate 1: 9600  (mechanical)
B13  MSR Chassis L8  Part Number: EL6002  Baudrate 1: 9600  (mechanical)
B14  MSR Chassis L10  Part Number: EL6022  Baudrate 1: 115.2k  Serial Interface 1: RS422  (mechanical)
B15  MSR Chassis L12  Part Number: EL9011  (mechanical)
V95  PemEnvCMsrRack1TempIn  (no BOM)
V96  PemEnvCMsrRack2TempIn  (no BOM)
V99  SysTimingCOMinM2  (no BOM)
V100  SysTimingCOMoutM2  (no BOM)
V101  SysFiberPolCorrIn  (no BOM)
V102  SysFiberPolCorrOut  (no BOM)
V103  SysTimingCOMinM5  (no BOM)
V104  SysTimingCOMoutM5  (no BOM)
V827  SysTimingCOMinM6  (no BOM)
V828  SysTimingCOMoutM6  (no BOM)
V839  SysTimingPtpIn  (no BOM)
V843  WeatherIn  (no BOM)
V844  WeatherOut  (no BOM)

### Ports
MSR

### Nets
AuxCFast: V99.?1(Link) V100.?1(Link) V103.?1(Link) V104.?1(Link) V827.?1(Link) V828.?1(Link)
AuxCStd: V95.?2(Link) V96.?2(Link) V101.?1(Link) V102.?1(Link) V839.?1(Link) V843.?1(Link) V844.?1(Link)
NetB7_Ebus: B7.Ebus(B) B8.Ebus(A)
NetB7_X1 In: B7.X1_In(A) ; port MSR
NetB8_Ebus: B8.Ebus(B) B9.Ebus(A)
NetB9_Ebus: B9.Ebus(B) B10.Ebus(A)
NetB9_Value: B9.Value(RTD_Inputs_Channel_1) V95.?1
NetB9_Value: B9.Value(RTD_Inputs_Channel_2) V96.?1  [a separate net that carries the same name]
NetB10_Ebus: B10.Ebus(B) B11#1.Ebus(A)
NetB11#1_Control Value for DC Master Clock: B11#1.Control_Value_for_DC_Master_Clock(­­External_Sync) V839.ControlValDcClock(DINT)
NetB11#1_Control value update toggle: B11#1.Control_value_update_toggle(­­External_Sync) V839.ControlValToggle(BOOL)
NetB11#1_Ebus: B11#1.Ebus(B) B12.Ebus(A)
NetB11#1_External device not connected: B11#1.External_device_not_connected(­­External_Sync) V839.ExtDeviceMissing(BOOL)
NetB11#1_External time stamp: B11#1.External_time_stamp(­­External_Sync) V839.ExternalTimestamp(ULINT)
NetB11#1_Internal time stamp: B11#1.Internal_time_stamp(­­External_Sync) V839.InternalTimestamp(ULINT)
NetB11#1_Sync Mode: B11#1.Sync_Mode(­­External_Sync) V839.SyncMode(WORD)
NetB11#1_Time stamp update toggle: B11#1.Time_stamp_update_toggle(­­External_Sync) V839.TimestampToggle(BOOL)
NetB12_Ctrl: B12.Ctrl(COM_Outputs_Channel_1) V844.Ctrl(WORD)
NetB12_Ctrl: B12.Ctrl(COM_Outputs_Channel_2) V100.Ctrl(WORD)  [a separate net that carries the same name]
NetB12_Data1In[0..21]: B12.Data1In[0..21](COM_Inputs_Channel_1) V843.D[0..21](BYTE)
NetB12_Data1Out[0..21]: B12.Data1Out[0..21](COM_Outputs_Channel_1) V844.D[0..21](BYTE)
NetB12_Data2In[0..21]: B12.Data2In[0..21](COM_Inputs_Channel_2) V99.D[0..21](BYTE)
NetB12_Data2Out[0..21]: B12.Data2Out[0..21](COM_Outputs_Channel_2) V100.D[0..21](BYTE)
NetB12_Ebus: B12.Ebus(B) B13.Ebus(A)
NetB12_Status: B12.Status(COM_Inputs_Channel_1) V843.Status(WORD)
NetB12_Status: B12.Status(COM_Inputs_Channel_2) V99.Status(WORD)  [a separate net that carries the same name]
NetB13_Ctrl: B13.Ctrl(COM_Outputs_Channel_1) V102.Ctrl(WORD)
NetB13_Data2In[0..21]: B13.Data2In[0..21](COM_Inputs_Channel_2) V101.D[0..21](BYTE)
NetB13_Data2Out[0..21]: B13.Data2Out[0..21](COM_Outputs_Channel_2) V102.D[0..21](BYTE)
NetB13_Ebus: B13.Ebus(B) B14.Ebus(A)
NetB13_Status: B13.Status(COM_Inputs_Channel_1) V101.Status(WORD)
NetB14_Ctrl: B14.Ctrl(COM_Outputs_Channel_1) V828.Ctrl(WORD)
NetB14_Ctrl: B14.Ctrl(COM_Outputs_Channel_2) V104.Ctrl(WORD)  [a separate net that carries the same name]
NetB14_Data1In[0..21]: B14.Data1In[0..21](COM_Inputs_Channel_1) V827.D[0..21](BYTE)
NetB14_Data1Out[0..21]: B14.Data1Out[0..21](COM_Outputs_Channel_1) V828.D[0..21](BYTE)
NetB14_Data2In[0..21]: B14.Data2In[0..21](COM_Inputs_Channel_2) V103.D[0..21](BYTE)
NetB14_Data2Out[0..21]: B14.Data2Out[0..21](COM_Outputs_Channel_2) V104.D[0..21](BYTE)
NetB14_Ebus: B14.Ebus(B) B15.Ebus(A)
NetB14_Status: B14.Status(COM_Inputs_Channel_1) V827.Status(WORD)
NetB14_Status: B14.Status(COM_Inputs_Channel_2) V103.Status(WORD)  [a separate net that carries the same name]

Not connected (* = marked no-connect by the designer): B7 X2 Out(C)*; B13 Data1In[0..21](COM_Inputs_Channel_1)* Data1Out[0..21](COM_Outputs_Channel_1)*

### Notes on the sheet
- EtherCAT Mapping: MSR
- Daniel Sigg

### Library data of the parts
B7 = CouplerEK1101: EtherCAT Coupler; Rail: Left; BoxNextB: DTWVYLGW; BoxPrev: LHTDNYMI; PortPrevFull: 1000/; Fullname: TIID^Vertex MSR (EtherCAT)^MSR Chassis L0 (EK1101); BoxPorts: Junction; BoxAddr: 1001; Disabled: False
B8 = TerminalEL6080: EtherCAT Terminal EL6080 Memory; Rail: Left; BoxNextB: QXEOUGJE; BoxPrev: DRMHDDTT; PortPrevFull: 1001/B; PortPrevShort: B; Fullname: TIID^Vertex MSR (EtherCAT)^MSR Chassis L0 (EK1101)^MSR Chassis L1 (EL6080); BoxAddr: 1002; Disabled: False
B9 = TerminalEL3202-0010: EtherCAT Terminal EL3202-0010 2-chn Temperature Input; Rail: Left; BoxNextB: QBNRREKQ; BoxPrev: DTWVYLGW; PortPrevFull: 1002/B; PortPrevShort: B; Fullname: TIID^Vertex MSR (EtherCAT)^MSR Chassis L0 (EK1101)^MSR Chassis L2 (EL3202-0010); BoxAddr: 1003; Disabled: False
B10 = TerminalEL9400: EtherCAT Terminal EL9400 Power; BoxType: TerminalPassive; Rail: Left; BoxNextB: UXPGGLQP; BoxPrev: QXEOUGJE; PortPrevShort: B; Fullname: TIID^Vertex MSR (EtherCAT)^MSR Chassis L0 (EK1101)^MSR Chassis L3 (EL9400); Disabled: False
B11#1 = TerminalEL6688: EtherCAT Terminal EL6688 Clock; Disabled: False
B11#2 = TerminalEL6688: EtherCAT Terminal EL6688 Clock; Rail: Left; BoxNextB: CYQBPVIK; BoxPrev: QBNRREKQ; PortPrevFull: 1003/B; PortPrevShort: B; Fullname: TIID^Vertex MSR (EtherCAT)^MSR Chassis L0 (EK1101)^MSR Chassis L4 (EL6688); BoxAddr: 1004; Disabled: False
B12 = TerminalEL6002: EtherCAT Terminal EL6002 Dual RS232; Rail: Left; BoxNextB: RTMBOGVS; BoxPrev: UXPGGLQP; PortPrevFull: 1004/B; PortPrevShort: B; Fullname: TIID^Vertex MSR (EtherCAT)^MSR Chassis L0 (EK1101)^MSR Chassis L6 (EL6002); BoxAddr: 1005; BoxSubType: 9101; Disabled: False
B13 = TerminalEL6002: EtherCAT Terminal EL6002 Dual RS232; Rail: Left; BoxNextB: DQXTOCMA; BoxPrev: CYQBPVIK; PortPrevFull: 1005/B; PortPrevShort: B; Fullname: TIID^Vertex MSR (EtherCAT)^MSR Chassis L0 (EK1101)^MSR Chassis L8 (EL6002); BoxAddr: 1006; BoxSubType: 9101; Disabled: False
B14 = TerminalEL6022: EtherCAT Terminal EL6022 Dual RS422; Rail: Left; BoxNextB: UIOOYRBM; BoxPrev: RTMBOGVS; PortPrevFull: 1006/B; PortPrevShort: B; Fullname: TIID^Vertex MSR (EtherCAT)^MSR Chassis L0 (EK1101)^MSR Chassis L10 (EL6022); BoxAddr: 1007; BoxSubType: 9103; Disabled: False
B15 = TerminalEL9011: EtherCAT Terminal EL9011 End; BoxType: TerminalPassive; Rail: Left; BoxPrev: DQXTOCMA; PortPrevShort: B; Fullname: TIID^Vertex MSR (EtherCAT)^MSR Chassis L0 (EK1101)^MSR Chassis L12 (EL9011); Disabled: False
V95 V96 = VariableInINT: INT; PLC: H1AuxCorner; Task: AuxCStd; Instance: H1AuxCorner Instance
V99 V103 V827 = Serial_EL6inData22Bfast: EL6inData22B; PLC: H1AuxCorner; Task: AuxCFast; BoxType: Variable; Instance: H1AuxCorner Instance
V100 V104 V828 = Serial_EL6outData22Bfast: EL6outData22B; PLC: H1AuxCorner; Task: AuxCFast; BoxType: Variable; Instance: H1AuxCorner Instance
V101 V843 = Serial_EL6inData22B: EL6inData22B; PLC: H1AuxCorner; Task: AuxCStd; BoxType: Variable; Instance: H1AuxCorner Instance
V102 V844 = Serial_EL6outData22B: EL6outData22B; PLC: H1AuxCorner; Task: AuxCStd; BoxType: Variable; Instance: H1AuxCorner Instance
V839 = Ptp_PtpInStruct: PtpInStruct; BoxType: Variable; Instance: H1AuxCorner Instance; PLC: H1AuxCorner; Task: AuxCStd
